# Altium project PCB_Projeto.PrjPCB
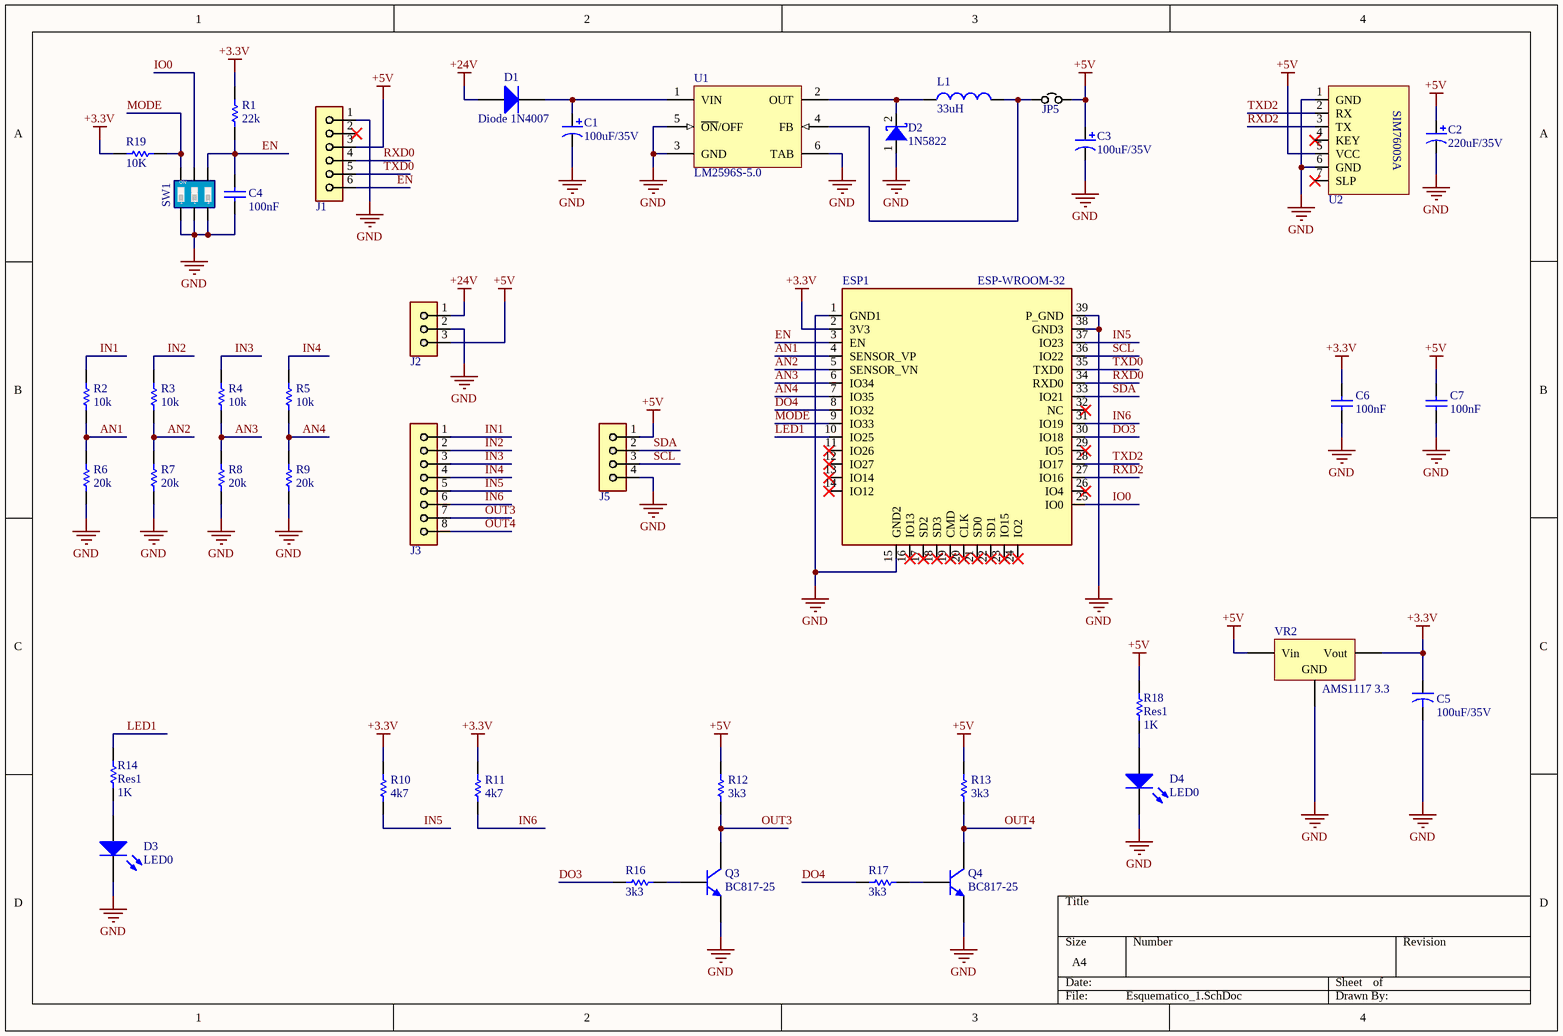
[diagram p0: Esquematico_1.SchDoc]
1 sheet, 42 parts. Net scope: global (net labels, ports and power ports of the same name join across sheets).
Board file: PCB_IoT.PcbDoc

## Sheet Esquematico_1.SchDoc
size A4

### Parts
C1  value 100uF/35V  [CAP_ELEC_1]  (hidden comment: CAP_ELEC)
C2  value 220uF/35V  [CAP_ELEC_3.5MM]  (hidden comment: CAP_ELEC)
C3  value 100uF/35V  [CAP_ELEC_1]  (hidden comment: CAP_ELEC)
C4  value 100nF  [CAP]  (hidden comment: Cap)
C5  value 100uF/35V  [CAP_ELEC_1]  (hidden comment: Cap2)
C6  value 100nF  [6-0805_M]  (hidden comment: Cap)
C7  value 100nF  [6-0805_M]  (hidden comment: Cap)
D1  Diode 1N4007  [DO214]
D2  1N5822  [DO214]
D3  LED0  [6-0805_M]
D4  LED0  [6-0805_M]
ESP1  ESP-WROOM-32  [ESP32-WROOM-32D]
J1  SIL_6  [SIL_6]  (value not drawn)
J2  SIL_3  [SIL_3]  (value not drawn)
J3  SIL_8  [SIL_8]  (value not drawn)
J5  SIL_4  [SIL_4]  (value not drawn)
JP5  JUMPER  [SIL_2]  (value not drawn)
L1  value 33uH  [INDUTOR_SMD]  (hidden comment: Inductor)
Q3  BC817-25  [SOT-23A_M]
Q4  BC817-25  [SOT-23A_M]
R1  value 22k  [6-0805_M]  (hidden comment: Res1)
R2  value 10k  [6-0805_M]  (hidden comment: Res1)
R3  value 10k  [6-0805_M]  (hidden comment: Res1)
R4  value 10k  [6-0805_M]  (hidden comment: Res1)
R5  value 10k  [6-0805_M]  (hidden comment: Res1)
R6  value 20k  [6-0805_M]  (hidden comment: Res1)
R7  value 20k  [6-0805_M]  (hidden comment: Res1)
R8  value 20k  [6-0805_M]  (hidden comment: Res1)
R9  value 20k  [6-0805_M]  (hidden comment: Res1)
R10  value 4k7  [6-0805_M]  (hidden comment: Res1)
R11  value 4k7  [6-0805_M]  (hidden comment: Res1)
R12  value 3k3  [6-0805_M]  (hidden comment: Res1)
R13  value 3k3  [6-0805_M]  (hidden comment: Res1)
R14  Res1  value 1K  [6-0805_M]
R16  value 3k3  [6-0805_M]  (hidden comment: Res1)
R17  value 3k3  [6-0805_M]  (hidden comment: Res1)
R18  Res1  value 1K  [6-0805_M]
R19  value 10K  [6-0805_M]  (hidden comment: Res1)
SW1  DIP_SWITCH_3  [DIP_6]  (value not drawn)
U1  LM2596S-5.0  [TS5B_M]
U2  SIM7600  [Modulo_SIM7600SA]  (value not drawn)
VR2  AMS1117 3.3  [SOT-223B_M]

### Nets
+3.3V: C5.1 C6.2 ESP1.2(3V3) R1.2 R10.1 R11.1 R19.2 VR2.3(Vout)
+5V: C2.1 C3.1 C7.2 J1.3 J2.3 J5.1 JP5.2 R12.1 R13.1 R18.1 U2.5(VCC) VR2.1(Vin)
+24V: D1.1(A) J2.1
GND: C1.2 C2.2 C3.2 C4.1 C5.2 C6.1 C7.1 D2.1 D3.2(K) D4.2(K) ESP1.1(GND1) ESP1.15(GND2) ESP1.38(GND3) ESP1.39(P_GND) J1.1 J2.2 J5.4 Q3.2(E) Q4.2(E) R6.1 R7.1 R8.1 R9.1 SW1.1 SW1.2 SW1.3 U1.3(GND) U1.5(~{ON}/OFF) U1.6(TAB) U2.1(GND) U2.6(GND) VR2.2(GND)
AN1: ESP1.4(SENSOR_VP) R2.1 R6.2
AN2: ESP1.5(SENSOR_VN) R3.1 R7.2
AN3: ESP1.6(IO34) R4.1 R8.2
AN4: ESP1.7(IO35) R5.1 R9.2
DO3: ESP1.30(IO18) R16.2
DO4: ESP1.8(IO32) R17.2
EN: C4.2 ESP1.3(EN) J1.6 R1.1 SW1.4
IN1: J3.1 R2.2
IN2: J3.2 R3.2
IN3: J3.3 R4.2
IN4: J3.4 R5.2
IN5: ESP1.37(IO23) J3.5 R10.2
IN6: ESP1.31(IO19) J3.6 R11.2
IO0: ESP1.25(IO0) SW1.5
LED1: ESP1.10(IO25) R14.1
MODE: ESP1.9(IO33) R19.1 SW1.6
OUT3: J3.7 Q3.3(C) R12.2
OUT4: J3.8 Q4.3(C) R13.2
RXD0: ESP1.34(RXD0) J1.4
RXD2: ESP1.27(IO16) U2.3(TX)
SCL: ESP1.36(IO22) J5.3
SDA: ESP1.33(IO21) J5.2
TXD0: ESP1.35(TXD0) J1.5
TXD2: ESP1.28(IO17) U2.2(RX)
NetC1_1: C1.1 D1.2(K) U1.1(VIN)
NetD2_2: D2.2 L1.1 U1.2(OUT)
NetD3_1: D3.1(A) R14.2
NetD4_1: D4.1(A) R18.2
NetJP5_1: JP5.1 L1.2 U1.4(FB)
NetQ3_1: Q3.1(B) R16.1
NetQ4_1: Q4.1(B) R17.1

Not connected (* = marked no-connect by the designer): ESP1 11(IO26)* 12(IO27)* 13(IO14)* 14(IO12)* 16(IO13)* 17(SD2)* 18(SD3)* 19(CMD)* 20(CLK)* 21(SD0)* 22(SD1)* 23(IO15)* 24(IO2)* 26(IO4)* 29(IO5)* 32(NC)*; J1 2*; U2 4(KEY)* 7(SLP)*

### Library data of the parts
C1-C3 = CAP_ELEC: Capacitor eletrolitico radial
C4 C6 C7 = Cap: Capacitor
C5 = Cap2: Capacitor
D1 = Diode 1N4007: 1 Amp General Purpose Rectifier
D3 D4 = LED0: Typical INFRARED GaAs LED
J3 = SIL_8: SIL 8 Connector
L1 = Inductor: Code_IEC: 1005
Q3 Q4 = BC817-25: NPN General Purpose Amplifier
R1-R14 R16-R19 = Res1: Resistor
SW1 = DIP_SWITCH_3: DIP SWITCH 3 WAYS
U1 = LM2596S-5.0: SIMPLE SWITCHER® Power Converter 150 KHz 3A Step-Down Voltage Regulator, 5-pin TO-263; Manufacturer: National Semiconductor; PackageTopMarking: NSUZXYTTE#*LM2596S*-5.0 P+; PowerWise: N
U2 = Modulo_SIM7600
VR2 = Volt Reg: Voltage Regulator; pin to pad: 1>3 2>1 3>2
